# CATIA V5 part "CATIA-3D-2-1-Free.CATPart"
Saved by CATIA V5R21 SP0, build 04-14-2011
Part number: CATIA-3D-2-1-Free
Bounding box of the stored display mesh (mm): x 0 to 125, y -19 to 19, z 0 to 85
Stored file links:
  C:\Users\Rasoul Mohammadi\Desktop\CATIA-Free\3D\CATIA-3D-2-1-Free.CATPart
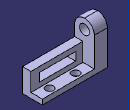
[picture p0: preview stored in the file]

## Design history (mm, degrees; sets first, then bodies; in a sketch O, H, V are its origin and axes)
Body1 (main body)
  Sketch1 on zx-plane, origin (0, 0, 0), H (-1, 0, 0), V (0, 0, 1)
    point P1 (0, 85)
    line L1 (0, 85) -> (0, 0)
    line L2 (0, 0) -> (-125, 0)
    line L3 (-125, 0) -> (-125, 10)
    line L4 (-125, 10) -> (-25, 10)
    line L5 (-25, 10) -> (-25, 85)
    line L6 (-25, 85) -> (0, 85)
    length L2 = 125
    length L6 = 25
    length L3 = 10
    length L1 = 85
    coincidence: P1 V
    vertical: L1 V, L3 V, L5 V
    horizontal: L2 H, L4 H, L6 H
  Pad1: profile Sketch1, direction (0, 1, 0), length 19, mirrored extent
  Fillet1: radius 19, on edge [face of Pad1 from Sketch1.L6 | end face of Pad1]; edge [start face of Pad1 | face of Pad1 from Sketch1.L6]
  Sketch2 on start face of Pad1, origin (0, -19, 0), H (1, 0, 0), V (0, 0, 1)
    projected line E1 (25, 10) -> (125, 10) from edge [start face of Pad1 | face of Pad1 from Sketch1.L4]
    point P1 (25, 10)
    projected line E2 (25, 66) -> (25, 10) from edge [start face of Pad1 | face of Pad1 from Sketch1.L5]
    projected line E3 (25, 45) -> (25, 10) from edge [start face of Pad1 | face of Pad1 from Sketch1.L5]
    point P4 (25, 10)
    point P5 (25, 45)
    line L1 (25, 45) -> (125, 45)
    line L2 (125, 45) -> (125, 10)
    line L3 (39, 35) -> (109, 35)
    line L4 (109, 35) -> (109, 19)
    line L5 (109, 19) -> (39, 19)
    line L6 (39, 19) -> (39, 35)
    length L2 = 35
    distance L3 L1 = 10
    length L4 = 16
    distance L4 L2 = 16
    length L3 = 70
    coincidence: P5 E2, P1 P4
    horizontal: L1 H, L3 H, L5 H
    vertical: L2 V, L4 V, L6 V
  Pad2: profile Sketch2, direction (0, 1, 0), length 16
  Sketch3 on face of Pad1 from Sketch1.L5, origin (25, 2.0005, 68.0684), H (0, 1, 0), V (0, 0, 1)
    point P1 (-2.0005, -2.0684)
    reference projected arc E1 centre (-2.0005, -2.0684) radius 19 from (16.9995, -2.0684) to (-2.0005, 16.9316) ccw from edge [face of Pad1 from Sketch1.L5 | face of Fillet1]
    concentricity: E1 P1
  Hole1: placed by Sketch3, at (25, 0, 66) direction (-1, 0, 0), diameter 19, through (limit type 6)
  Sketch4 on face of Pad1 from Sketch1.L4, origin (107.0026, 5.7324, 10), H (1, 0, 0), V (0, 1, 0)
    point P1 (-7.0026, 2.2676)
    reference projected line E1 (-82.0026, 13.2676) -> (17.9974, 13.2676) from edge [face of Pad1 from Sketch1.L4 | end face of Pad1]
    reference projected line E2 (17.9974, -24.7324) -> (17.9974, 13.2676) from edge [face of Pad2 | face of Pad1 from Sketch1.L4]
    distance P1 E1 = 11
    distance P1 E2 = 25
  Hole2: placed by Sketch4, at (100, 8, 10) direction (0, 0, -1), diameter 15, through (limit type 6)
  Sketch5 on face of Pad1 from Sketch1.L4, origin (66.2763, 7.2791, 10), H (1, 0, 0), V (0, 1, 0)
    point P1 (-16.2763, 0.7209)
    reference projected line E1 (58.7237, -26.2791) -> (58.7237, 11.7209) from edge [face of Pad2 | face of Pad1 from Sketch1.L4]
    reference projected line E2 (-41.2763, 11.7209) -> (58.7237, 11.7209) from edge [face of Pad1 from Sketch1.L4 | end face of Pad1]
    distance E1 P1 = 75
    distance P1 E2 = 11
  Hole3: placed by Sketch5, at (50, 8, 10) direction (0, 0, -1), diameter 15, through (limit type 6)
